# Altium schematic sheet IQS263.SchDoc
size A3; CheckedBy: XXX; Author: DO NOT USE THIS PARAMETER; CompanyName: Azoteq (Pty) Ltd; Engineer: DO NOT USE THIS PARAMETER; SheetNumber: 1; SheetTotal: 2; Sheet_Title: Sheet x
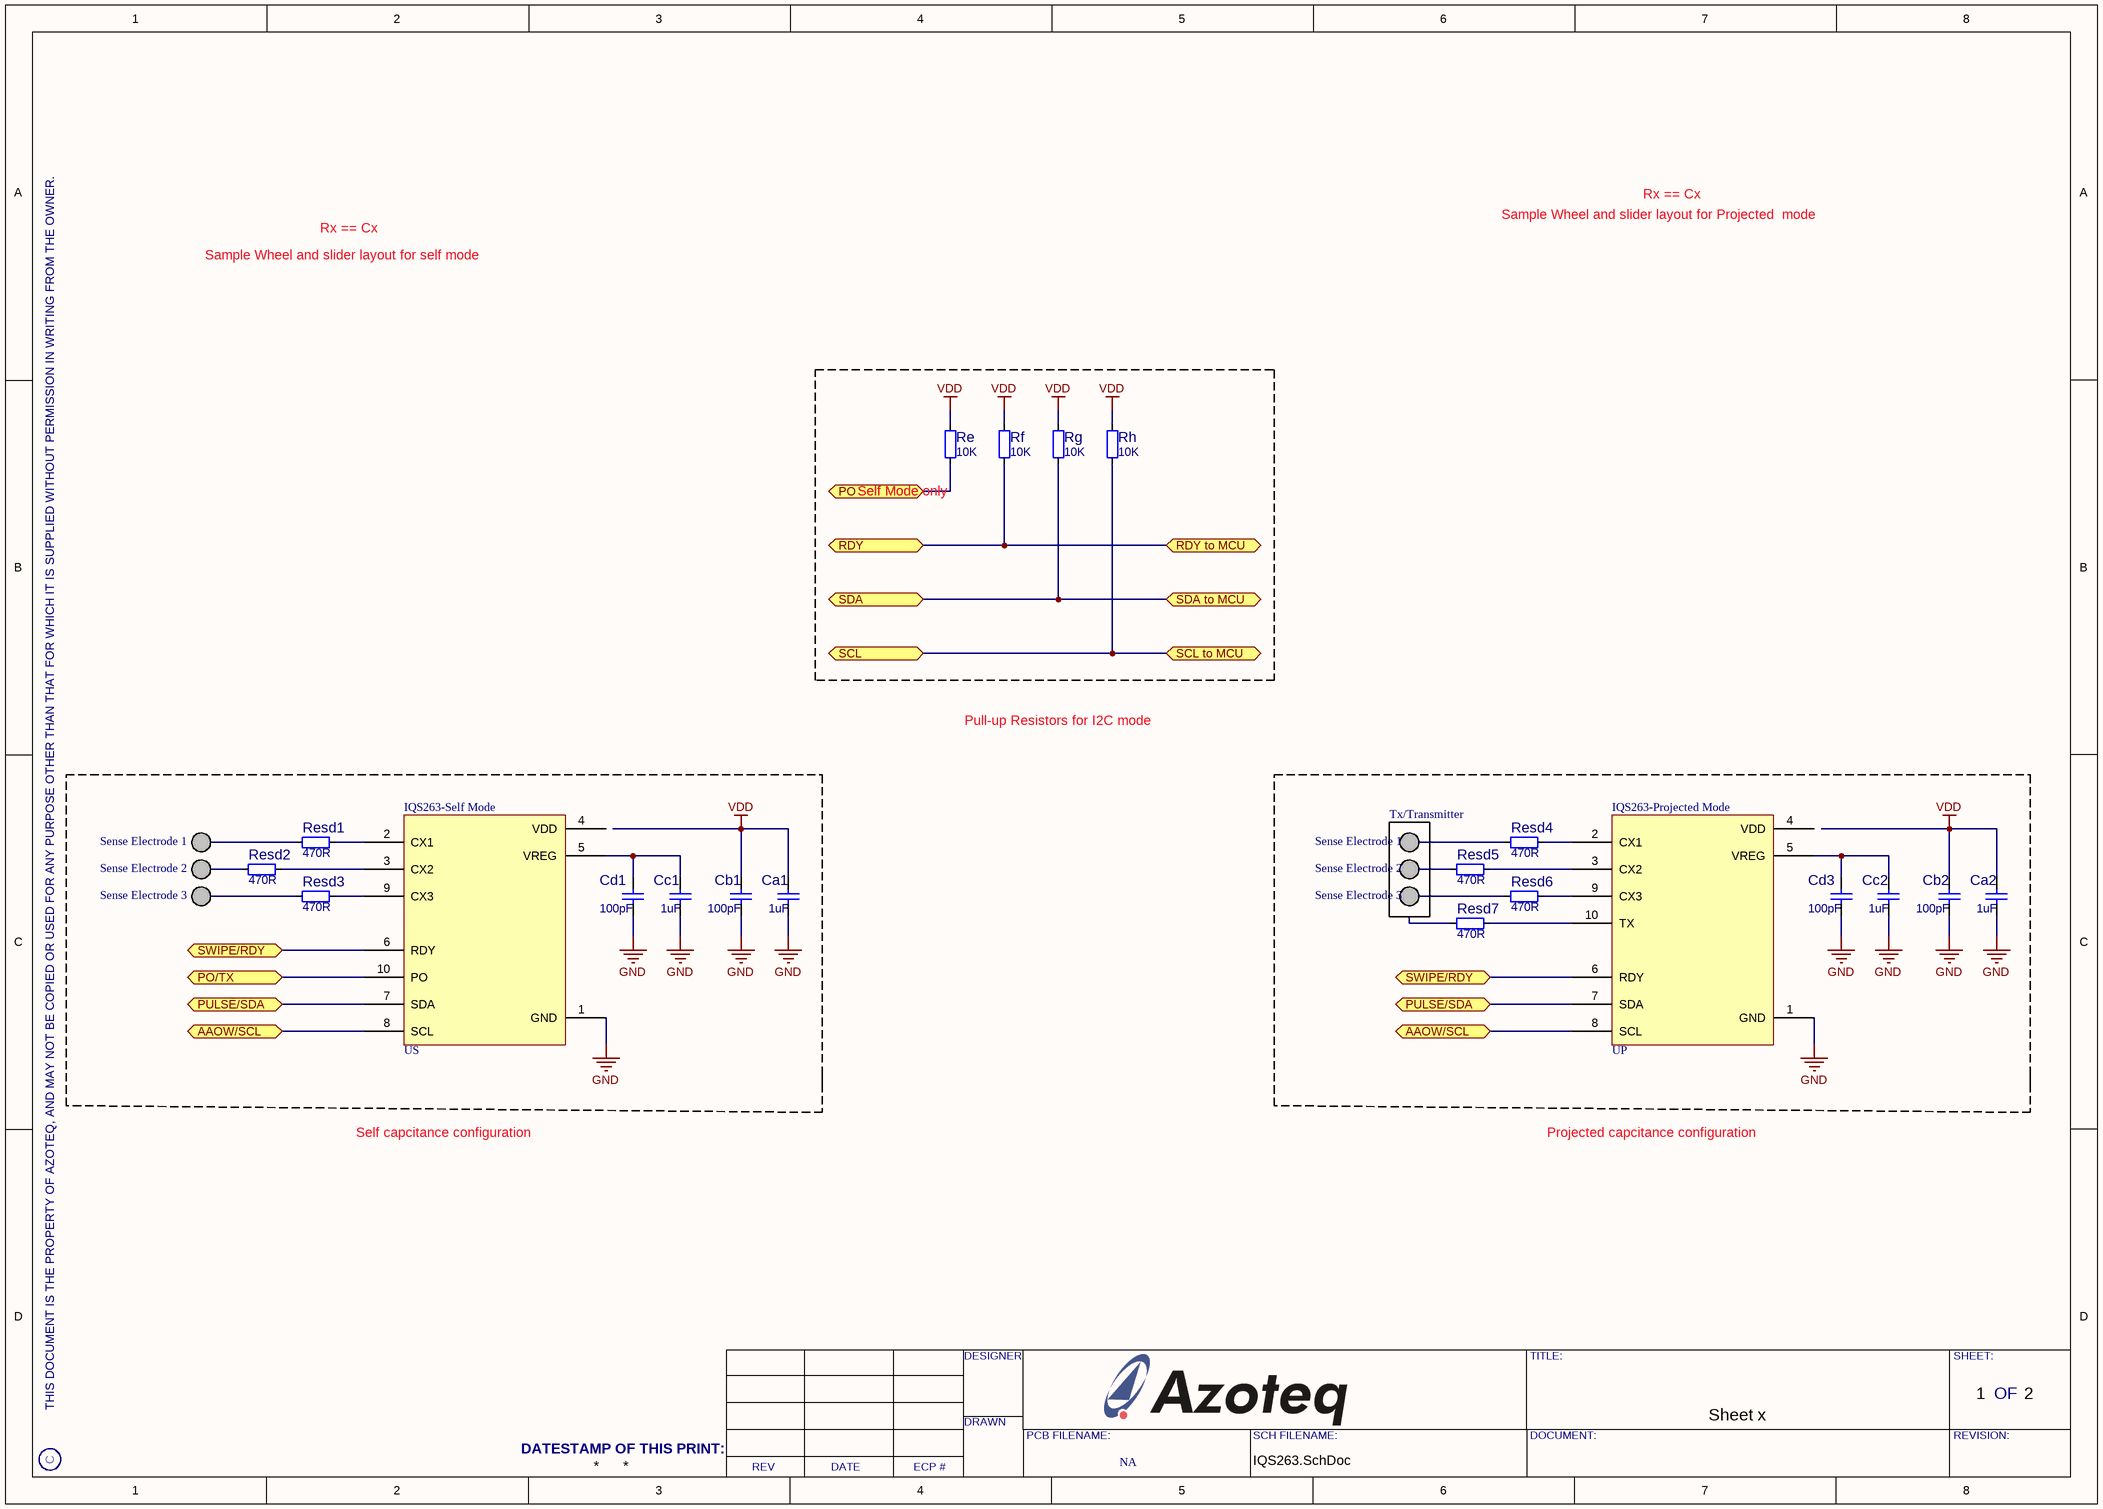
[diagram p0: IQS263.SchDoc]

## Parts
Ca1  1uF  [C-0402]
Ca2  1uF  [C-0402]
Cb1  100pF  [C-0402]
Cb2  100pF  [C-0402]
Cc1  1uF  [C-0402]
Cc2  1uF  [C-0402]
Cd1  100pF  [C-0402]
Cd3  100pF  [C-0402]
IQS263-Projected_Mode  UP
IQS263-Self_Mode  US
Re  10K  [R-0603]
Resd1  470R  [R-0603]
Resd2  470R  [R-0603]
Resd3  470R  [R-0603]
Resd4  470R  [R-0603]
Resd5  470R  [R-0603]
Resd6  470R  [R-0603]
Resd7  470R  [R-0603]
Rf  10K  [R-0603]
Rg  10K  [R-0603]
Rh  10K  [R-0603]

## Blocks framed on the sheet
Self Mode only: Re Rf Rg Rh

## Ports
AAOW/SCL, PO, PO/TX, PULSE/SDA, RDY, RDY to MCU, SCL, SCL to MCU, SDA, SDA to MCU, SWIPE/RDY

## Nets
GND: Ca1.2 Ca2.2 Cb1.2 Cb2.2 Cc1.2 Cc2.2 Cd1.2 Cd3.2 IQS263-Projected_Mode.1(GND) IQS263-Self_Mode.1(GND)
VDD: Ca1.1 Ca2.1 Cb1.1 Cb2.1 Re.1 Rf.1 Rg.1 Rh.1
AAOW/SCL: IQS263-Projected_Mode.8(SCL) IQS263-Self_Mode.8(SCL) ; port AAOW/SCL
PO: Re.2 ; port PO
PO/TX: IQS263-Self_Mode.10(PO) ; port PO/TX
PULSE/SDA: IQS263-Projected_Mode.7(SDA) IQS263-Self_Mode.7(SDA) ; port PULSE/SDA
RDY: Rf.2 ; port RDY, port RDY to MCU
SCL: Rh.2 ; port SCL, port SCL to MCU
SDA: Rg.2 ; port SDA, port SDA to MCU
SWIPE/RDY: IQS263-Projected_Mode.6(RDY) IQS263-Self_Mode.6(RDY) ; port SWIPE/RDY
NetCc1_1: Cc1.1 Cd1.1 IQS263-Self_Mode.5(VREG)
NetCc2_1: Cc2.1 Cd3.1 IQS263-Projected_Mode.5(VREG)
NetIQS263-Projected_Mode_2: IQS263-Projected_Mode.2(CX1) Resd4.2
NetIQS263-Projected_Mode_3: IQS263-Projected_Mode.3(CX2) Resd5.2
NetIQS263-Projected_Mode_9: IQS263-Projected_Mode.9(CX3) Resd6.2
NetIQS263-Projected_Mode_10: IQS263-Projected_Mode.10(TX) Resd7.2
NetIQS263-Self_Mode_2: IQS263-Self_Mode.2(CX1) Resd1.2
NetIQS263-Self_Mode_3: IQS263-Self_Mode.3(CX2) Resd2.2
NetIQS263-Self_Mode_9: IQS263-Self_Mode.9(CX3) Resd3.2

Not connected (* = marked no-connect by the designer): IQS263-Projected_Mode 4(VDD); IQS263-Self_Mode 4(VDD); Resd1 1; Resd2 1; Resd3 1; Resd4 1; Resd5 1; Resd6 1; Resd7 1

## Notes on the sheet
- Rx == Cx
- Sample Wheel and slider layout for Projected  mode
- Sample Wheel and slider layout for self mode
- Pull-up Resistors for I2C mode
- (near Resd2) Sense Electrode 1
- (near Resd5) Sense Electrode 1
- Tx/Transmitter
- (near Resd2) Sense Electrode 2
- (near Resd2) Sense Electrode 3
- Sense Electrode 2
- Sense Electrode 3
- Self capcitance configuration
- Projected capcitance configuration
- NA

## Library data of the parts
Ca1 Ca2 Cb1 Cb2 Cc1 Cc2 Cd1 Cd3 = CAP 12pF 0402 CER NPO 5% 50V: Capacitor, Ceramic, 12pF, 0402, NPO, 5%, 50V; Generated_By: GHM; Pin_Count: 2
IQS263-Projected_Mode IQS263-Self_Mode = Component_1
Re Resd1-Resd7 Rf Rg Rh = RES 4K7 0603 1% 0.1W: Int_Part_Number: RES0003; Tolerance: 1%; Wattage: 0.1W; Generated_By: GHM; Value: 4.7K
